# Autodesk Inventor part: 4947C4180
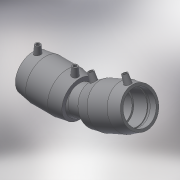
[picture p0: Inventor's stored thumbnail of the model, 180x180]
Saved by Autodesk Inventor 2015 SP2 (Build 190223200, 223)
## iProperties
Created: 2017-06
Part Number: 4947C4180
Material: Generic
Description: PLASSON ADJUSTABLE ELBOW 180
Document SubType Name: Modeling
Designer: KIM
Mass: 55.0731 g
Surface Area: 148.067 cm^2
Volume: 55.0731 cm^3
Density: 1 g/cm^3
Appearance: Default
Author: KIM
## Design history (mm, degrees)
derived "4947C4.ipt"
feature "Solid1::4947C4.ipt"
tag "TaggingFeature1"
body "Solid1"
other parameters: "d0" = 204.4, "d2" = 224, "d3" = 104, "d4" = 52, "d5" = 201.6, "d8" = 168 deg, "d10" = 41.6, "d11" = 13.86667, "d29" = 128, "d30" = 15, "d31" = 81.76, "d34" = 5 deg, "d41" = 4, "d42" = 14, "d43" = 0, "d48" = 162, "d49" = 24 deg, "d50" = 511, "d51" = 78 deg, "d52" = 90 deg, "d55" = 50.2, "d57" = 168 deg, "d58" = 10.04, "d60" = 60.33179, "d62" = 3, "d63" = 0, "L_" = 511, "L_1" = 104, "D_" = 224, "A_" = 128, "d_2" = 12, "L_0" = 148, "d54" = 100.4, "d59" = 201.10598
